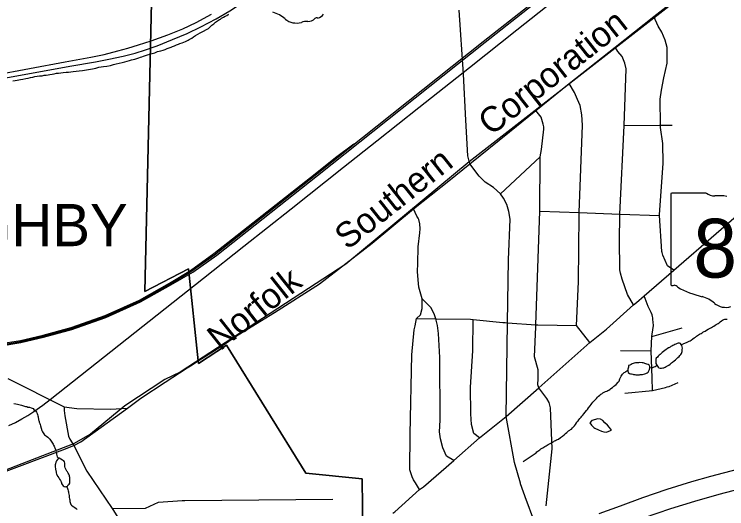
# Model space of a CAD drawing. Extents: x 0 to 44.3, y 0 to 22.
# Drawn here: x 5.6 to 7.197, y 18.401 to 19.51 of the extents above; entities that cross this region are included whole.
import ezdxf

# ---------------------------------------------------------------- set-up
doc = ezdxf.new("R2010")
doc.units = 0
for name, color, linetype in [('GM_X_City_Street', 7, 'Continuous'), ('GM_X_Corporation', 7, 'Continuous'), ('GM_X_Corporation_Text', 7, 'Continuous'), ('GM_X_County_Road', 7, 'Continuous'), ('GM_X_Interstate_Route', 7, 'Continuous'), ('GM_X_Minor_Lake', 7, 'Continuous'), ('GM_X_Minor_River', 7, 'Continuous'), ('GM_X_Rail_Line', 7, 'Continuous'), ('GM_X_Rail_Line_Text', 7, 'Continuous'), ('GM_X_State_Location', 7, 'Continuous'), ('GM_X_State_Route', 7, 'Continuous'), ('GM_X_State_Shield', 7, 'Continuous'), ('GM_X_US_Route', 7, 'Continuous')]:
    doc.layers.add(name, color=color, linetype=linetype)

msp = doc.modelspace()

# ---------------------------------------------------------------- linework, layer by layer
at = {"layer": 'GM_X_City_Street'}
for p, q in [((7.049, 19.2609), (7.0753, 19.2612)), ((6.6901, 19.1067), (6.779, 19.1902)), ((7.0291, 18.7869), (7.0974, 18.8064)), ((6.9589, 18.7557), (7.0276, 18.7553))]:
    msp.add_line(p, q, dxfattribs=at)
for points in [[(7.0786, 18.9357), (7.0648, 18.9453), (7.054, 18.9698), (7.0532, 18.9724), (7.0525, 18.9752), (7.0522, 18.9774), (7.0468, 19.0587), (7.0467, 19.0597), (7.0547, 19.1755), (7.0542, 19.22), (7.0491, 19.2557), (7.049, 19.2609), (7.0478, 19.3189), (7.0513, 19.3391), (7.0566, 19.3674), (7.0637, 19.4), (7.0642, 19.4236), (7.0635, 19.4354), (7.0597, 19.4517), (7.0516, 19.4694), (7.0439, 19.4832), (7.0338, 19.5045)], [(6.9881, 18.8582), (6.9746, 18.8816), (6.963, 18.9156), (6.9594, 18.929), (6.9581, 18.9368), (6.9577, 18.9421), (6.9569, 18.9992), (6.9577, 19.0617), (6.9678, 19.2602), (6.972, 19.3873), (6.9688, 19.4002), (6.9626, 19.4148), (6.9536, 19.4261), (6.9471, 19.4355)], [(6.8908, 18.7735), (6.8605, 18.8116), (6.865, 18.9099), (6.8666, 19.0592), (6.8668, 19.0648), (6.8739, 19.2612), (6.8722, 19.2844), (6.8685, 19.3048), (6.8626, 19.3184), (6.8558, 19.3342), (6.8439, 19.3543)], [(6.7924, 18.4076), (6.8057, 18.5355), (6.8027, 18.6272), (6.7997, 18.6389), (6.794, 18.648), (6.7761, 18.6722), (6.7743, 18.6791), (6.7749, 18.6929), (6.7749, 18.7122), (6.7668, 18.7418), (6.7692, 18.809), (6.7694, 18.8133), (6.7786, 19.0678), (6.779, 19.1902), (6.7821, 19.2062), (6.7873, 19.252), (6.7872, 19.2539), (6.7872, 19.2573), (6.7862, 19.2634), (6.7815, 19.2791), (6.7694, 19.2941)], [(6.9678, 19.2602), (7.0465, 19.2609), (7.049, 19.2609)], [(6.5858, 18.509), (6.5696, 18.5191), (6.5611, 18.5373), (6.5561, 18.5578), (6.5537, 18.5734), (6.555, 18.5996), (6.5541, 18.7398), (6.5511, 18.7941), (6.5491, 18.8115), (6.545, 18.8267), (6.5426, 18.836), (6.5347, 18.8517), (6.5148, 18.8717), (6.5072, 18.8977), (6.5054, 18.9143), (6.5043, 18.9331), (6.5052, 18.951), (6.5057, 18.9879), (6.5093, 19.0194), (6.5101, 19.0288), (6.5095, 19.04), (6.5072, 19.0494), (6.5055, 19.0525), (6.5024, 19.0569), (6.4956, 19.0734)], [(6.7786, 19.0678), (6.8668, 19.0648), (6.9577, 19.0617), (7.0468, 19.0587)], [(7.0307, 18.6658), (7.0299, 18.6942), (7.0276, 18.7553), (7.0291, 18.7869), (7.0325, 18.807), (7.0329, 18.8108), (7.0323, 18.82), (7.032, 18.8246), (7.0315, 18.829), (7.0311, 18.8317), (7.0299, 18.8358), (7.0279, 18.841), (7.0209, 18.8547), (7.012, 18.8784)], [(6.509, 18.4437), (6.4995, 18.4589), (6.4955, 18.4661), (6.4925, 18.4726), (6.4873, 18.4884), (6.488, 18.568), (6.4917, 18.7462), (6.4967, 18.8017), (6.4989, 18.8112), (6.5019, 18.8271), (6.5113, 18.836), (6.5146, 18.85), (6.5148, 18.8717)], [(6.5019, 18.8271), (6.545, 18.8267), (6.6227, 18.826), (6.629, 18.8253), (6.6953, 18.8188), (6.701, 18.8182), (6.7059, 18.8179), (6.7694, 18.8133), (6.7737, 18.813), (6.8605, 18.8116)], [(6.6435, 18.56), (6.6308, 18.5697), (6.625, 18.5898), (6.6237, 18.6137), (6.6233, 18.6733), (6.6285, 18.755), (6.629, 18.8253)], [(6.9692, 18.6598), (7.0307, 18.6658), (7.0598, 18.6725), (7.0639, 18.6739), (7.0685, 18.6753), (7.0884, 18.6843)], [(5.7119, 18.6293), (5.7407, 18.6258), (5.8159, 18.6244), (5.8542, 18.6261)], [(5.8196, 18.4015), (5.8948, 18.402), (5.9239, 18.4155), (5.9771, 18.4193), (5.9829, 18.4193), (6.3146, 18.4224)]]:
    msp.add_lwpolyline(points, dxfattribs=at)
at = {"layer": 'GM_X_Corporation'}
for points in [[(6.3816, 18.3424), (6.3804, 18.468), (6.2537, 18.4805), (6.0759, 18.768), (6.0133, 18.7265), (6.0126, 18.7328), (5.9906, 18.939), (5.8933, 18.8882), (5.9054, 19.4386), (5.9198, 20.0555), (5.9324, 20.6242), (5.9378, 20.9), (4.9066, 20.9)], [(8.2369, 18.3305), (8.2337, 18.6163), (8.648, 18.6417), (8.6432, 18.7252), (8.6245, 18.7283), (8.6223, 18.8598), (8.8575, 18.8766), (8.845, 19.3119), (8.9, 19.3141), (8.9, 20.9), (5.9378, 20.9), (5.9324, 20.6242), (5.9198, 20.0555), (5.9054, 19.4386), (5.8933, 18.8882), (5.9906, 18.939), (6.0126, 18.7328), (6.0133, 18.7265), (6.0759, 18.768), (6.2537, 18.4805), (6.3804, 18.468), (6.3816, 18.3424)]]:
    msp.add_lwpolyline(points, dxfattribs=at)
at = {"layer": 'GM_X_County_Road'}
msp.add_line((5.5861, 18.6932), (5.7119, 18.6293), dxfattribs=at)
for points in [[(5.7119, 18.6293), (5.7122, 18.6209), (5.7134, 18.6089), (5.7217, 18.5633), (5.7246, 18.5566), (5.7338, 18.5425)], [(5.7338, 18.5425), (5.7628, 18.4849), (5.8196, 18.4015), (5.8213, 18.3991), (5.8647, 18.3301), (5.879, 18.3159), (5.9051, 18.3001), (5.957, 18.2691)]]:
    msp.add_lwpolyline(points, dxfattribs=at)
at = {"layer": 'GM_X_Interstate_Route'}
for points in [[(6.9117, 18.3899), (6.9589, 18.4072), (7.0095, 18.4263), (7.0642, 18.4445), (7.1191, 18.4619), (7.1618, 18.4739), (7.2213, 18.4895), (7.2721, 18.5013), (7.3742, 18.5218), (7.5974, 18.5656), (7.8563, 18.6165), (8.3098, 18.7047), (8.5339, 18.7485), (8.7866, 18.7974)], [(6.8642, 18.323), (6.9278, 18.3495), (7.0109, 18.3806), (7.0718, 18.4015), (7.1259, 18.4178), (7.1807, 18.4334), (7.2289, 18.4466), (7.2805, 18.4589), (7.3786, 18.4788), (7.6018, 18.5226), (7.8551, 18.5721), (8.3142, 18.6617), (8.3268, 18.6641)]]:
    msp.add_lwpolyline(points, dxfattribs=at)
at = {"layer": 'GM_X_Minor_Lake'}
for points in [[(7.0387, 18.7265), (7.0423, 18.7205), (7.0435, 18.7187), (7.0455, 18.7168), (7.0478, 18.7161), (7.0508, 18.7158), (7.0539, 18.7166), (7.0561, 18.7171), (7.0592, 18.7183), (7.0614, 18.7195), (7.0648, 18.7215), (7.0674, 18.7231), (7.0704, 18.7254), (7.0734, 18.7278), (7.076, 18.7298), (7.0794, 18.7325), (7.0823, 18.7349), (7.0853, 18.7376), (7.0879, 18.74), (7.0909, 18.7423), (7.092, 18.7443), (7.0942, 18.7466), (7.0957, 18.7493), (7.0964, 18.7512), (7.0971, 18.7532), (7.0974, 18.7558), (7.0977, 18.7581), (7.0981, 18.7608), (7.0964, 18.7672), (7.0952, 18.7691), (7.0936, 18.7713), (7.0913, 18.7724), (7.0886, 18.7724), (7.086, 18.7715), (7.083, 18.7699), (7.0811, 18.7691), (7.0788, 18.7679), (7.0762, 18.7667), (7.0743, 18.7655), (7.0724, 18.7647), (7.0706, 18.7635), (7.0679, 18.7619), (7.0669, 18.7614)], [(7.0669, 18.7614), (7.0586, 18.7556), (7.0556, 18.7532), (7.0526, 18.7513), (7.0504, 18.7489), (7.0478, 18.747), (7.0459, 18.745), (7.0437, 18.743), (7.0418, 18.7411), (7.0392, 18.7387), (7.0385, 18.7361), (7.0382, 18.733), (7.0383, 18.7311), (7.0383, 18.7273), (7.0387, 18.7265)], [(6.9771, 18.7223), (6.9772, 18.7204), (6.9769, 18.7181), (6.9765, 18.7158), (6.9758, 18.7135), (6.9759, 18.7101), (6.9764, 18.7063), (6.9795, 18.7045), (6.9818, 18.7034), (6.9837, 18.7031), (6.9868, 18.7024), (6.9887, 18.702), (6.9914, 18.7017), (6.9937, 18.7014), (6.9971, 18.7015), (6.9998, 18.7012), (7.0017, 18.7012), (7.0036, 18.7017), (7.0062, 18.7017), (7.0085, 18.7022), (7.0138, 18.7031), (7.0161, 18.7043), (7.0187, 18.7055), (7.0213, 18.7074), (7.0224, 18.7098), (7.0239, 18.7128), (7.0249, 18.7174), (7.0248, 18.7197), (7.0232, 18.7227), (7.0209, 18.7242), (7.0182, 18.7253), (7.014, 18.7267), (7.0121, 18.727), (7.0101, 18.7277), (7.0079, 18.728), (7.0078, 18.728)], [(7.0078, 18.728), (7.0021, 18.7287), (6.9999, 18.7282), (6.9972, 18.7281), (6.9949, 18.7281), (6.993, 18.7277), (6.99, 18.7272), (6.9877, 18.7264), (6.9854, 18.7259), (6.9828, 18.7247), (6.9802, 18.7231), (6.9775, 18.7223), (6.9775, 18.7223), (6.9771, 18.7223)], [(6.8948, 18.5991), (6.8907, 18.5938), (6.8945, 18.5885), (6.8991, 18.5832), (6.9018, 18.5815)], [(6.9387, 18.5772), (6.9348, 18.5828), (6.9298, 18.5885), (6.9244, 18.5937), (6.9198, 18.599), (6.9141, 18.602), (6.9088, 18.6023), (6.8948, 18.5991)], [(6.9018, 18.5815), (6.9102, 18.5776), (6.9167, 18.575), (6.922, 18.5736), (6.9277, 18.5729), (6.9334, 18.5745), (6.9387, 18.5772)], [(5.7011, 18.5145), (5.6997, 18.5142), (5.6971, 18.5116), (5.6949, 18.5081), (5.6937, 18.5054), (5.6927, 18.5016), (5.6923, 18.499), (5.6923, 18.4959), (5.6924, 18.494), (5.6928, 18.491), (5.6929, 18.4899)], [(5.6929, 18.4899), (5.694, 18.483), (5.6944, 18.4811), (5.6952, 18.4785), (5.6983, 18.4732), (5.7006, 18.4701), (5.7021, 18.4675), (5.7041, 18.4645), (5.7053, 18.4611), (5.706, 18.4592), (5.7064, 18.4573), (5.7076, 18.455), (5.7099, 18.4524), (5.7126, 18.4509), (5.7145, 18.4501), (5.7168, 18.4505), (5.7194, 18.4513), (5.7213, 18.4544), (5.7232, 18.4563), (5.7246, 18.4586), (5.725, 18.4616), (5.7253, 18.4647), (5.7253, 18.467), (5.7253, 18.4692), (5.7249, 18.4711), (5.7245, 18.473), (5.7241, 18.4749), (5.7229, 18.4783), (5.7214, 18.481), (5.7194, 18.4836), (5.7183, 18.4855), (5.7148, 18.4927), (5.714, 18.4954), (5.7136, 18.4977), (5.7139, 18.5007), (5.7139, 18.503), (5.7131, 18.506), (5.7112, 18.5087), (5.7089, 18.5102), (5.7011, 18.5145)]]:
    msp.add_lwpolyline(points, dxfattribs=at)
at = {"layer": 'GM_X_Minor_River'}
for points in [[(5.9384, 19.4309), (5.9429, 19.4325), (5.9475, 19.4344), (5.952, 19.436), (5.9554, 19.4376), (5.9596, 19.4391), (5.9637, 19.4407), (5.9682, 19.4423), (5.9716, 19.4438), (5.9766, 19.4458), (5.9803, 19.4469), (5.9841, 19.4485), (5.9875, 19.4501), (5.9902, 19.4516), (5.9928, 19.4528), (5.9954, 19.4543), (5.9985, 19.4563), (6.0022, 19.459), (6.0067, 19.462), (6.012, 19.4648), (6.0169, 19.4682), (6.0233, 19.471), (6.0331, 19.4764), (6.0358, 19.4779), (6.038, 19.4802), (6.0403, 19.4822), (6.0433, 19.4852), (6.0474, 19.4883), (6.0516, 19.4918), (6.0561, 19.4949), (6.0606, 19.4976), (6.0629, 19.4984), (6.0651, 19.501), (6.0693, 19.503), (6.0731, 19.5053), (6.0765, 19.5072), (6.0795, 19.5088), (6.0817, 19.51)], [(5.5972, 19.3602), (5.6025, 19.361), (5.6067, 19.3618), (5.6105, 19.3623), (5.6146, 19.3631), (5.6199, 19.3643), (5.626, 19.3655), (5.6317, 19.3667), (5.637, 19.3678), (5.6423, 19.3687), (5.6464, 19.3698), (5.6514, 19.3707), (5.6567, 19.3715), (5.6627, 19.3719), (5.6677, 19.3727), (5.6722, 19.3731), (5.6764, 19.3739), (5.6805, 19.3747), (5.6851, 19.3756), (5.69, 19.3764), (5.6953, 19.3772), (5.6999, 19.3776), (5.7048, 19.3784), (5.7101, 19.3788), (5.7169, 19.3797), (5.7222, 19.3801), (5.7275, 19.3805), (5.7328, 19.381), (5.7389, 19.3818), (5.7461, 19.3826), (5.7533, 19.3838), (5.776, 19.3875), (5.7832, 19.3887), (5.79, 19.3907), (5.8003, 19.3923), (5.8082, 19.3935), (5.8158, 19.3951), (5.8226, 19.3971), (5.8291, 19.3987), (5.8355, 19.4002), (5.8419, 19.4015), (5.848, 19.403), (5.8533, 19.4046), (5.8586, 19.4058), (5.8635, 19.4074), (5.8703, 19.409), (5.8749, 19.4105), (5.8794, 19.4121), (5.8835, 19.4133), (5.8866, 19.4144), (5.89, 19.416), (5.8945, 19.4172), (5.8994, 19.4188), (5.9043, 19.4203), (5.9096, 19.4219), (5.9153, 19.4235), (5.9217, 19.4258), (5.9289, 19.4274), (5.9339, 19.4294), (5.9384, 19.4309)], [(7.0958, 18.7681), (7.1012, 18.7712), (7.1031, 18.772), (7.105, 18.7728), (7.1072, 18.774), (7.1103, 18.7752), (7.1129, 18.7764), (7.1152, 18.7776), (7.1178, 18.7788), (7.1215, 18.7816), (7.1245, 18.7839), (7.1271, 18.7859), (7.1297, 18.7879), (7.132, 18.7895), (7.1342, 18.791), (7.1361, 18.7922), (7.138, 18.793), (7.1399, 18.7942), (7.1421, 18.7954), (7.144, 18.7966), (7.147, 18.7986), (7.1489, 18.7994), (7.1523, 18.8014), (7.1556, 18.8034), (7.1575, 18.8046), (7.1601, 18.8058), (7.1632, 18.8074), (7.1658, 18.809), (7.1684, 18.8102), (7.1714, 18.8122), (7.174, 18.8138), (7.1778, 18.8165), (7.1804, 18.8181), (7.1826, 18.8201), (7.1853, 18.822), (7.1882, 18.824), (7.1909, 18.8252), (7.1928, 18.8257), (7.1954, 18.8261), (7.1981, 18.8262)], [(7.0249, 18.7174), (7.0283, 18.7171), (7.0314, 18.7176), (7.0344, 18.7188), (7.037, 18.72), (7.0389, 18.7212), (7.041, 18.7228)], [(6.7412, 18.5067), (6.77, 18.5263), (6.7718, 18.5282), (6.7741, 18.5298), (6.7759, 18.5318), (6.7782, 18.5333), (6.7804, 18.5349), (6.7834, 18.5365), (6.7853, 18.5377), (6.7872, 18.5389), (6.7898, 18.5401), (6.7924, 18.5417), (6.7947, 18.5433), (6.7973, 18.5449), (6.7999, 18.5461), (6.8018, 18.5473), (6.8045, 18.5488), (6.8071, 18.5504), (6.8097, 18.552), (6.8116, 18.5532), (6.8135, 18.5537), (6.8161, 18.5552), (6.8199, 18.5572), (6.8251, 18.5604), (6.827, 18.562), (6.8296, 18.564), (6.8326, 18.5667), (6.8344, 18.5679), (6.8363, 18.5695), (6.8393, 18.5718), (6.8426, 18.5753), (6.8453, 18.5769), (6.8471, 18.5785), (6.8494, 18.5797), (6.8516, 18.5824), (6.8546, 18.5852), (6.8564, 18.5871), (6.8583, 18.5898), (6.8608, 18.5937), (6.8623, 18.5964), (6.8641, 18.598), (6.866, 18.6003), (6.8682, 18.603), (6.8708, 18.6065), (6.8726, 18.6088), (6.8745, 18.6108), (6.8774, 18.6139), (6.88, 18.6174), (6.883, 18.6209), (6.8852, 18.6236), (6.8878, 18.6271), (6.8911, 18.6318), (6.8937, 18.6349), (6.8951, 18.6368), (6.8974, 18.6396), (6.8988, 18.6415), (6.9007, 18.6438), (6.9033, 18.6462), (6.9055, 18.6481), (6.9077, 18.6509), (6.91, 18.6532), (6.9126, 18.6556), (6.9148, 18.6575), (6.9171, 18.6587), (6.9197, 18.6607), (6.9227, 18.6623), (6.9257, 18.6635), (6.9287, 18.6647), (6.9306, 18.6659), (6.9332, 18.6671), (6.9358, 18.6691), (6.9377, 18.6707), (6.9411, 18.673), (6.9441, 18.6754), (6.9467, 18.677), (6.9493, 18.6793), (6.9541, 18.6844), (6.9563, 18.6871), (6.9577, 18.6925), (6.9599, 18.6964), (6.961, 18.6983), (6.9635, 18.7029), (6.9654, 18.7045), (6.9673, 18.7061), (6.9695, 18.7073), (6.9714, 18.7085), (6.9759, 18.7119)], [(5.5997, 18.6369), (5.6038, 18.6361), (5.6076, 18.6354), (5.6107, 18.6343), (5.6134, 18.6336), (5.6164, 18.6328), (5.6187, 18.6321), (5.6213, 18.6314), (5.6236, 18.631), (5.6259, 18.6303), (5.6286, 18.6299), (5.6312, 18.6288), (5.6343, 18.6285), (5.6381, 18.6274), (5.6404, 18.6266), (5.6427, 18.6255), (5.6446, 18.6232), (5.6469, 18.6214), (5.6488, 18.6195), (5.6504, 18.6176), (5.6519, 18.6142), (5.6523, 18.6119), (5.6531, 18.6096), (5.6539, 18.607), (5.6543, 18.6051), (5.6547, 18.6032), (5.6551, 18.6005), (5.6555, 18.5986), (5.6559, 18.5967), (5.6563, 18.5948), (5.6579, 18.5918), (5.6586, 18.5899), (5.6594, 18.5865)], [(5.6594, 18.5865), (5.6622, 18.5766), (5.6638, 18.5732), (5.6649, 18.5709), (5.6665, 18.5687), (5.6684, 18.5668), (5.6703, 18.5653), (5.673, 18.5634), (5.6753, 18.5612), (5.6783, 18.5585), (5.6799, 18.5566), (5.6814, 18.5544), (5.683, 18.5525), (5.6845, 18.5502), (5.6861, 18.548), (5.6876, 18.5457), (5.6884, 18.5438), (5.6899, 18.5412), (5.6907, 18.5393), (5.6915, 18.5374), (5.6927, 18.534), (5.6938, 18.5309), (5.6946, 18.5279), (5.6954, 18.5249), (5.6954, 18.523), (5.6955, 18.5203), (5.6963, 18.5176), (5.6997, 18.5142)], [(5.7178, 18.4508), (5.7191, 18.4483), (5.7198, 18.4464), (5.7206, 18.4437), (5.7214, 18.4411), (5.7218, 18.4392), (5.7222, 18.4365), (5.7226, 18.4335), (5.7231, 18.4304), (5.7235, 18.4285), (5.7235, 18.4259), (5.7239, 18.4232), (5.7247, 18.4206), (5.7251, 18.4175), (5.7255, 18.4149), (5.7263, 18.413), (5.7275, 18.4107), (5.729, 18.4088), (5.7321, 18.4062), (5.734, 18.4051), (5.7363, 18.4036), (5.739, 18.4013), (5.7412, 18.3994)]]:
    msp.add_lwpolyline(points, dxfattribs=at)
at = {"layer": 'GM_X_Rail_Line'}
for points in [[(5.5651, 18.768), (5.6149, 18.7757), (5.6654, 18.7876), (5.729, 18.8053), (5.8051, 18.8321), (5.8822, 18.8667), (5.9499, 18.9049), (5.9965, 18.9325), (6.0494, 18.9705), (6.2783, 19.1515), (6.6511, 19.4487), (7.068, 19.777), (7.5069, 20.1249), (7.8816, 20.4181), (8.1527, 20.6341), (8.4876, 20.9)], [(5.5655, 18.7657), (5.6154, 18.7734), (5.666, 18.7854), (5.7297, 18.8031), (5.806, 18.8299), (5.8833, 18.8646), (5.9511, 18.9029), (6.0009, 18.9316), (6.0543, 18.9694), (6.2802, 19.1482), (6.6557, 19.4469), (7.0742, 19.7774), (7.5083, 20.1231), (7.883, 20.4163), (8.1542, 20.6323), (8.4913, 20.9)], [(5.5884, 18.5876), (5.6031, 18.5945), (5.6177, 18.6024), (5.6308, 18.6101), (5.644, 18.6187), (5.6646, 18.633), (5.681, 18.6455), (6.0246, 18.9178), (6.1153, 18.9899), (6.2212, 19.0736), (6.3387, 19.1668), (6.4128, 19.2255), (6.507, 19.3002), (6.6206, 19.3902), (6.7271, 19.4749), (7.0841, 19.7577), (7.3744, 19.988), (7.7059, 20.251), (7.9801, 20.4681), (7.9935, 20.4787), (8.0055, 20.4876), (8.0206, 20.4989), (8.0359, 20.5097)], [(8.9, 20.3376), (8.8492, 20.3004), (8.7465, 20.2194), (8.7066, 20.1916), (8.5746, 20.144), (8.3312, 20.0564), (7.2758, 19.673), (7.2263, 19.6512), (6.6197, 19.179), (6.3434, 18.949), (5.9721, 18.7068), (5.938, 18.691), (5.8479, 18.6314), (5.7712, 18.5681), (5.7335, 18.5462), (5.4742, 18.4465)], [(5.5648, 18.7703), (5.6145, 18.778), (5.6649, 18.7899), (5.7283, 18.8075), (5.8043, 18.8343), (5.8812, 18.8688), (5.9487, 18.9069), (5.9958, 18.9349), (6.0478, 18.9731), (6.2749, 19.152), (6.3202, 19.1888), (6.3612, 19.2189)]]:
    msp.add_lwpolyline(points, dxfattribs=at)
at = {"layer": 'GM_X_State_Route'}
for points in [[(5.9166, 19.4377), (5.9204, 19.439), (5.9554, 19.4531), (5.9881, 19.4666), (6.0186, 19.4812), (6.0528, 19.4997), (6.0836, 19.5175), (6.118, 19.5394), (6.146, 19.5589), (6.1697, 19.5776), (6.1891, 19.5939), (6.2094, 19.6114), (6.2349, 19.6352), (6.3022, 19.7061), (6.3516, 19.758), (6.4095, 19.8211), (6.5325, 19.9546)], [(6.6127, 19.2724), (6.6071, 19.3751), (6.5977, 19.5191)], [(5.5536, 19.3728), (5.7142, 19.403), (5.7718, 19.4133), (5.8019, 19.4192), (5.8325, 19.4275), (5.8551, 19.4339), (5.8787, 19.4409), (5.9069, 19.4499), (5.9446, 19.4637), (5.9783, 19.4773), (6.0082, 19.4912), (6.0424, 19.5097)], [(6.7027, 18.6077), (6.7761, 18.6722), (6.8908, 18.7735), (6.9275, 18.8037), (6.9881, 18.8582), (6.9949, 18.863), (7.012, 18.8784), (7.0786, 18.9357), (7.2684, 19.1001), (7.4824, 19.2875), (7.6406, 19.4243), (7.7233, 19.4971)], [(5.0084, 19.1891), (5.037, 19.2075), (5.0664, 19.2245), (5.0972, 19.2418), (5.1159, 19.2503), (5.154, 19.268), (5.1858, 19.2805), (5.2326, 19.2961), (5.2684, 19.3072), (5.3018, 19.3156), (5.3396, 19.3235), (5.3922, 19.3331), (5.4669, 19.345), (5.5562, 19.3624), (5.7246, 19.393), (5.7823, 19.4033), (5.8123, 19.4092), (5.8446, 19.416), (5.8711, 19.4227), (5.8943, 19.43), (5.9166, 19.4377)], [(6.6215, 19.174), (6.617, 19.1925), (6.6127, 19.2724)], [(6.7027, 18.6077), (6.7059, 18.8179), (6.7081, 18.9593), (6.7121, 19.0501), (6.7089, 19.0672), (6.7041, 19.0828), (6.6973, 19.0973), (6.6901, 19.1067), (6.6743, 19.121), (6.6559, 19.133), (6.6421, 19.1466), (6.6215, 19.174)], [(6.4493, 18.3907), (6.4531, 18.3941), (6.509, 18.4437), (6.5179, 18.4502), (6.5858, 18.509), (6.6435, 18.56), (6.7027, 18.6077)], [(6.7351, 18.458), (6.722, 18.5046), (6.7027, 18.6077)], [(6.7486, 18.4197), (6.7354, 18.457), (6.7351, 18.458)], [(6.763, 18.381), (6.7499, 18.4159), (6.7486, 18.4197)]]:
    msp.add_lwpolyline(points, dxfattribs=at)
at = {"layer": 'GM_X_State_Shield'}
for p, q in [((7.0718, 19.1052), (7.0718, 18.9051)), ((7.1516, 19.1086), (7.0744, 19.1086))]:
    msp.add_line(p, q, dxfattribs=at)
for centre, radius, start, end in [((6.1645, 19.4527), 0.0632, 47.1842, 75.836), ((6.2589, 19.515), 0.0214, 268.777, 315.5493), ((6.2782, 19.4956), 0.00601, 65.7517, 132.6484), ((6.2756, 19.5232), 0.0226, 282.8732, 323.2771), ((6.2328, 19.53), 0.0401, 230.7004, 286.2918), ((6.256, 19.4608), 0.0329, 85.6951, 111.2099), ((7.0748, 19.1056), 0.00305, 98.1301, 188.1301), ((7.17, 19.1319), 0.0296, 231.6195, 271.1119), ((7.1798, 18.9963), 0.1064, 80.4867, 94.9883), ((7.0748, 18.9046), 0.00308, 171.9584, 258.3066), ((7.0753, 18.9251), 0.0235, 267.339, 280.6039), ((7.0801, 18.8935), 0.00848, 29.7484, 93.2717), ((7.1872, 19.0733), 0.2019, 240.4129, 257.1985), ((7.127, 18.8152), 0.0632, 47.1842, 75.836), ((7.1953, 18.8925), 0.0401, 230.7004, 286.2918)]:
    msp.add_arc(centre, radius, start, end, dxfattribs=at)
at = {"layer": 'GM_X_US_Route'}
for p, q in [((6.6215, 19.174), (6.7103, 19.2461)), ((6.5743, 19.1363), (6.6215, 19.174))]:
    msp.add_line(p, q, dxfattribs=at)
for points in [[(6.7103, 19.2461), (6.7694, 19.2941), (6.8439, 19.3543), (6.9471, 19.4355), (7.0338, 19.5045), (7.1647, 19.6067), (7.1749, 19.6148)], [(6.0966, 18.7871), (6.1057, 18.7934), (6.1836, 18.8407), (6.2847, 18.9054), (6.4024, 18.9967), (6.4956, 19.0734), (6.5743, 19.1363)], [(6.0635, 18.7646), (6.0736, 18.7711), (6.0966, 18.7871)], [(5.9956, 18.7216), (6.0128, 18.7322), (6.0635, 18.7646)], [(5.5576, 18.476), (5.5595, 18.4766), (5.7096, 18.5327), (5.7338, 18.5425), (5.7499, 18.5511), (5.8542, 18.6261), (5.884, 18.6488), (5.939, 18.685), (5.9879, 18.7167), (5.9956, 18.7216)]]:
    msp.add_lwpolyline(points, dxfattribs=at)

# ---------------------------------------------------------------- texts
at = {"layer": 'GM_X_Corporation_Text'}
msp.add_text('WILLOUGHBY', height=0.0947, rotation=0, dxfattribs=at).set_placement((5.0102, 18.9895))
at = {"layer": 'GM_X_Rail_Line_Text'}
for s, height, rotation, p in [('Corporation', 0.056629, 38.2943, (6.6688, 19.2355)), ('Southern', 0.05663, 38.3763, (6.3472, 18.9796)), ('Norfolk', 0.05663, 38.4568, (6.0617, 18.7532))]:
    msp.add_text(s, height=height, rotation=rotation, dxfattribs=at).set_placement(p)
at = {"layer": 'GM_X_State_Location'}
msp.add_text('84', height=0.000189, rotation=0, dxfattribs=at).set_placement((7.1529, 18.978))
at = {"layer": 'GM_X_State_Shield'}
msp.add_text('84', height=0.13184, dxfattribs=at).set_placement((7.1224, 18.9192))

doc.saveas('drawing.dxf')
